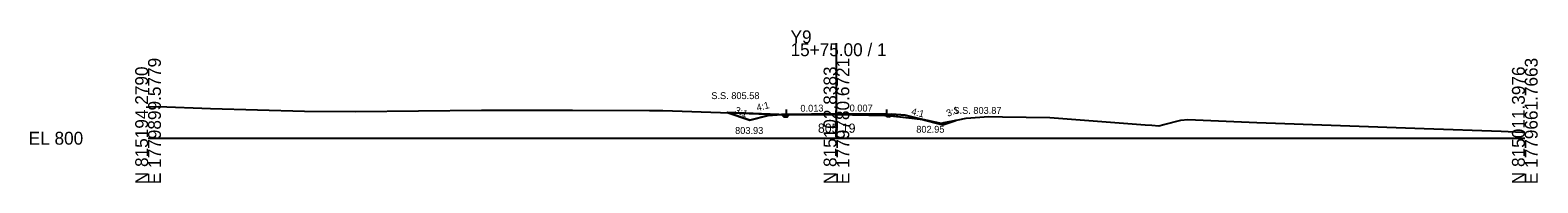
# Model space of a CAD drawing. Extents: x -26 to 1303, y -10 to 9523.
# Drawn here: x -25.7 to 302.8, y 9490.3 to 9523.5 of the extents above; entities that cross this region are included whole.
import ezdxf

# ---------------------------------------------------------------- set-up
doc = ezdxf.new("R2010")
doc.units = 0
for name, color, linetype in [('Exist Cross Section Cell', 7, 'Continuous'), ('Exist XS Center Line Elevation Label', 7, 'Continuous'), ('Exist XS Ground Line', 7, 'Continuous'), ('Prop XS Ditch Slope Text', 7, 'Continuous'), ('Prop XS Ditch Standard Text', 7, 'Continuous'), ('Prop XS Dump Level', 7, 'Continuous'), ('Prop XS Earthwork Shape', 7, 'Continuous'), ('Prop XS EOT Tick Mark', 7, 'Continuous'), ('Prop XS Finish Grade', 7, 'Continuous'), ('Prop XS Finish Grade Earthwork', 7, 'Continuous'), ('Prop XS Finish Grade Pavement', 7, 'Continuous'), ('Prop XS Pvmt Edge Slope', 7, 'Continuous'), ('Prop XS SE Text', 7, 'Continuous'), ('Prop XS Side Slope Text', 7, 'Continuous'), ('Prop XS SS Elevation Text', 7, 'Continuous'), ('Prop XS Subgrade Earthwork', 7, 'Continuous'), ('Scratch_Level_4', 7, 'Continuous')]:
    doc.layers.add(name, color=color, linetype=linetype)

msp = doc.modelspace()

# ---------------------------------------------------------------- linework, layer by layer
at = {"layer": 'Exist Cross Section Cell'}
for p, q in [((150, 9500), (150, 9520.65)), ((0, 9500), (150, 9500)), ((150, 9500), (300, 9500))]:
    msp.add_line(p, q, dxfattribs=at)
at = {"layer": 'Exist XS Ground Line'}
for p, q in [((0, 9506.81), (2.18, 9506.88)), ((2.18, 9506.88), (13.6, 9506.5)), ((13.6, 9506.5), (34.12, 9505.86)), ((34.12, 9505.86), (45.19, 9505.8)), ((45.19, 9505.8), (72.69, 9506.09)), ((72.69, 9506.09), (78.91, 9506.13)), ((78.91, 9506.13), (92.51, 9506.12)), ((92.51, 9506.12), (109.23, 9506.06)), ((109.23, 9506.06), (112.2, 9506.05)), ((112.2, 9506.05), (116.35, 9505.92)), ((116.35, 9505.92), (139.32, 9505.12)), ((139.32, 9505.12), (143.76, 9505.16)), ((143.76, 9505.16), (149.99, 9505.19)), ((149.99, 9505.19), (160.55, 9504.97)), ((160.55, 9504.97), (161.2, 9504.95)), ((161.2, 9504.95), (161.54, 9504.91)), ((161.54, 9504.91), (168.85, 9504.09)), ((178.29, 9504.36), (183.21, 9504.75)), ((183.21, 9504.75), (186.2, 9504.64)), ((186.2, 9504.64), (196.49, 9504.49)), ((196.49, 9504.49), (217.26, 9502.94)), ((168.85, 9504.09), (172.55, 9503.31)), ((172.55, 9503.31), (172.98, 9503.21)), ((172.98, 9503.21), (173.41, 9503.32)), ((173.41, 9503.32), (178.29, 9504.36)), ((217.26, 9502.94), (218.74, 9502.84)), ((218.74, 9502.84), (220.25, 9502.68)), ((220.25, 9502.68), (221.32, 9503.01)), ((221.32, 9503.01), (225.04, 9503.96)), ((225.04, 9503.96), (226.59, 9504.06)), ((226.59, 9504.06), (241.61, 9503.41)), ((241.61, 9503.41), (278.04, 9502.12)), ((278.04, 9502.12), (294.85, 9501.51)), ((294.85, 9501.51), (299.48, 9501.34)), ((299.48, 9501.34), (300, 9501.32))]:
    msp.add_line(p, q, dxfattribs=at)
at = {"layer": 'Prop XS Dump Level'}
for p, q in [((139.15, 9505.22), (150, 9505.35)), ((150, 9505.35), (161, 9505.27))]:
    msp.add_line(p, q, dxfattribs=at)
at = {"layer": 'Prop XS Earthwork Shape'}
for points in [[(139.32, 9504.64), (139.32, 9505.12), (126.2, 9505.58), (131.15, 9503.93), (135.15, 9504.93), (138.04, 9505.14), (138.56, 9504.63)], [(161, 9504.69), (161, 9504.96), (161.2, 9504.95), (161.54, 9504.91), (161.79, 9504.88), (161.59, 9504.68)], [(161.79, 9504.88), (168.45, 9504.14), (165, 9505), (162.1, 9505.2)], [(173.22, 9502.94), (176, 9503.87), (173.41, 9503.32), (172.98, 9503.21), (172.55, 9503.31), (168.85, 9504.09), (168.45, 9504.14)]]:
    msp.add_lwpolyline(points, close=True, dxfattribs=at)
at = {"layer": 'Prop XS EOT Tick Mark'}
for p, q in [((139.15, 9505.22), (139.15, 9506.22)), ((161, 9505.27), (161, 9506.27))]:
    msp.add_line(p, q, dxfattribs=at)
at = {"layer": 'Prop XS Finish Grade'}
for p, q in [((139.15, 9505.22), (138.04, 9505.14)), ((161, 9505.27), (162.1, 9505.2))]:
    msp.add_line(p, q, dxfattribs=at)
at = {"layer": 'Prop XS Finish Grade Earthwork'}
for p, q in [((131.15, 9503.93), (126.2, 9505.58)), ((135.15, 9504.93), (131.15, 9503.93)), ((138.04, 9505.14), (135.15, 9504.93)), ((162.1, 9505.2), (165, 9505)), ((165, 9505), (173.22, 9502.94)), ((173.22, 9502.94), (176, 9503.87))]:
    msp.add_line(p, q, dxfattribs=at)
at = {"layer": 'Prop XS Finish Grade Pavement'}
for p, q in [((139.15, 9505.22), (150, 9505.35)), ((150, 9505.35), (161, 9505.27))]:
    msp.add_line(p, q, dxfattribs=at)
at = {"layer": 'Prop XS Pvmt Edge Slope'}
for p, q in [((139.15, 9505.22), (138.56, 9504.63)), ((161, 9505.27), (161.59, 9504.68))]:
    msp.add_line(p, q, dxfattribs=at)
at = {"layer": 'Prop XS Subgrade Earthwork'}
for p, q in [((138.56, 9504.63), (138.04, 9505.14)), ((138.56, 9504.63), (139.32, 9504.64)), ((139.32, 9504.64), (139.32, 9505.12)), ((161, 9504.69), (161, 9504.96)), ((161, 9504.69), (161.59, 9504.68)), ((161.59, 9504.68), (162.1, 9505.2))]:
    msp.add_line(p, q, dxfattribs=at)
at = {"layer": 'Scratch_Level_4'}
for points in [[(138.56, 9504.63), (138.04, 9505.14), (135.15, 9504.93), (131.15, 9503.93), (126.2, 9505.58), (139.32, 9505.12), (139.32, 9504.64)], [(161, 9504.96), (161.2, 9504.95), (161.54, 9504.91), (161.79, 9504.88), (161.59, 9504.68), (161, 9504.69)], [(173.41, 9503.32), (176, 9503.87), (173.22, 9502.94), (168.45, 9504.14), (168.85, 9504.09), (172.55, 9503.31), (172.98, 9503.21)]]:
    msp.add_lwpolyline(points, close=True, dxfattribs=at)

# ---------------------------------------------------------------- texts
at = {"layer": 'Exist Cross Section Cell'}
for s, p in [('Y9', (140, 9520.65)), ('15+75.00 / 1', (140, 9517.85)), ('EL 800', (-26, 9498.6))]:
    msp.add_text(s, height=2.8, dxfattribs=at).set_placement(p)
for s, p in [('N 815194.2790', (0, 9490)), ('E 1779899.5779', (2.8, 9490)), ('N 815102.8383', (150, 9490)), ('E 1779780.6721', (152.8, 9490)), ('N 815011.3976', (300, 9490)), ('E 1779661.7663', (302.8, 9490))]:
    msp.add_text(s, height=2.8, rotation=90, dxfattribs=at).set_placement(p)
at = {"layer": 'Exist XS Center Line Elevation Label'}
msp.add_text('805.19', height=2, dxfattribs=at).set_placement((145.97, 9501.19))
at = {"layer": 'Prop XS Ditch Slope Text'}
for rotation, p in [(14.0362, (132.78, 9505.88)), (345.9638, (166.21, 9505.17))]:
    msp.add_text('4:1', height=1.5, rotation=rotation, dxfattribs=at).set_placement(p)
at = {"layer": 'Prop XS Ditch Standard Text'}
for s, p in [('803.93', (127.92, 9500.93)), ('802.95', (167.4, 9501.19))]:
    msp.add_text(s, height=1.5, dxfattribs=at).set_placement(p)
at = {"layer": 'Prop XS Dump Level'}
for s, height, p in [('Case1', 0.04, (135.15, 9504.89)), ('Eop', 0.3, (139.32, 9504.82)), ('Eop', 0.3, (161.2, 9504.65)), ('Case1', 0.04, (165, 9504.96))]:
    msp.add_text(s, height=height, dxfattribs=at).set_placement(p)
at = {"layer": 'Prop XS SE Text'}
for s, rotation, p in [('0.013', 0.7162, (142.16, 9505.75)), ('0.007', 359.5703, (152.87, 9505.83))]:
    msp.add_text(s, height=1.5, rotation=rotation, dxfattribs=at).set_placement(p)
at = {"layer": 'Prop XS Side Slope Text'}
for rotation, p in [(337.6812, (127.69, 9505.55)), (20.6648, (174.28, 9504.64))]:
    msp.add_text('3:1', height=1.5, rotation=rotation, dxfattribs=at).set_placement(p)
at = {"layer": 'Prop XS SS Elevation Text'}
for s, p in [('S.S. 805.58', (122.74, 9508.51)), ('S.S. 803.87', (175.49, 9505.3))]:
    msp.add_text(s, height=1.5, dxfattribs=at).set_placement(p)

doc.saveas('drawing.dxf')
